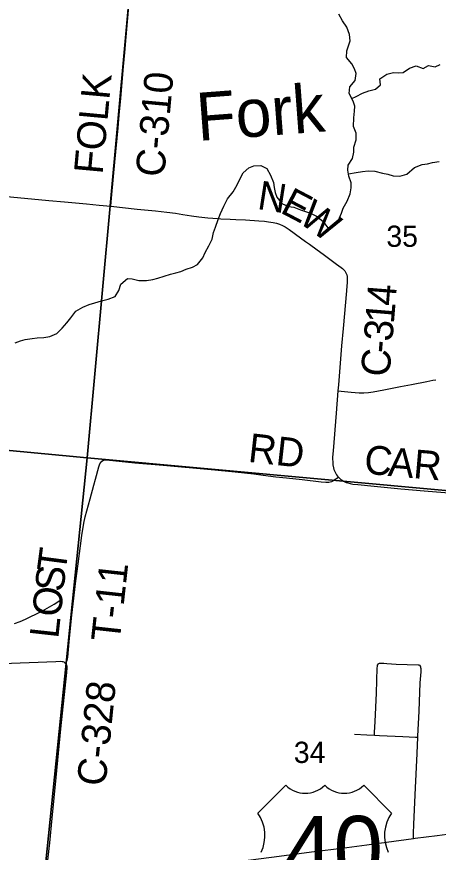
# Model space of a CAD drawing. Extents: x 831 to 1552, y 430 to 870.
# Drawn here: x 1326.79 to 1343.42, y 727.92 to 760.87 of the extents above; entities that cross this region are included whole.
import ezdxf

# ---------------------------------------------------------------- set-up
doc = ezdxf.new("R2010")
doc.units = 0
for name, color, linetype in [('GM_X_Corporation', 7, 'Continuous'), ('GM_X_County_Road', 7, 'Continuous'), ('GM_X_County_Road_Text', 7, 'Continuous'), ('GM_X_Minor_River', 7, 'Continuous'), ('GM_X_Minor_River_Text', 7, 'Continuous'), ('GM_X_Section_Text', 7, 'Continuous'), ('GM_X_Township_Road', 7, 'Continuous'), ('GM_X_Township_Road_Text', 7, 'Continuous'), ('GM_X_US_Location', 7, 'Continuous'), ('GM_X_US_Route', 7, 'Continuous'), ('GM_X_US_Shield', 7, 'Continuous')]:
    doc.layers.add(name, color=color, linetype=linetype)

msp = doc.modelspace()

# ---------------------------------------------------------------- linework, layer by layer
at = {"layer": 'GM_X_Corporation'}
for points in [[(1311.293, 765.037), (1331.382, 763.355), (1329.567, 743.48), (1309.391, 745.383)], [(1331.382, 763.355), (1350.153, 761.603), (1348.747, 741.721), (1329.567, 743.48)], [(1309.391, 745.383), (1329.567, 743.48), (1327.468, 722.912), (1307.365, 724.655)], [(1329.567, 743.48), (1348.747, 741.721), (1347.89, 720.702), (1327.468, 722.912)]]:
    msp.add_lwpolyline(points, close=True, dxfattribs=at)
at = {"layer": 'GM_X_County_Road'}
for points in [[(1330.507, 753.392), (1330.529, 753.708), (1330.657, 755.129), (1330.785, 756.488), (1330.829, 756.982), (1330.891, 757.662), (1331.003, 758.898), (1331.053, 759.454), (1331.11, 760.072), (1331.202, 761.123), (1331.371, 763.04), (1331.398, 763.338)], [(1313.508, 754.996), (1313.902, 754.958), (1314.52, 754.899), (1315.51, 754.81), (1316.315, 754.736), (1316.748, 754.701), (1317.119, 754.672), (1318.415, 754.564), (1318.724, 754.536), (1319.094, 754.496), (1319.65, 754.432), (1320.33, 754.363), (1321.009, 754.292), (1321.503, 754.241), (1322.431, 754.151), (1323.544, 754.044), (1324.596, 753.945), (1328.059, 753.623), (1328.678, 753.565), (1329.111, 753.524), (1329.544, 753.485), (1330.044, 753.438), (1330.507, 753.392)], [(1330.507, 753.392), (1331.546, 753.285), (1332.263, 753.215), (1332.706, 753.165), (1333.058, 753.115), (1333.348, 753.07), (1333.687, 753.012), (1333.967, 752.975), (1334.331, 752.937), (1334.521, 752.921), (1334.714, 752.908), (1334.841, 752.902), (1335.206, 752.886), (1335.426, 752.875), (1335.813, 752.857), (1336.341, 752.824), (1336.563, 752.805), (1336.726, 752.786), (1336.911, 752.757), (1337.033, 752.728), (1337.153, 752.69), (1337.268, 752.639), (1337.378, 752.579), (1337.535, 752.475), (1337.986, 752.149), (1338.186, 752.004), (1338.338, 751.895), (1338.639, 751.674), (1338.874, 751.503), (1339.093, 751.344), (1339.406, 751.115), (1339.588, 750.981), (1339.641, 750.94), (1339.696, 750.887), (1339.729, 750.842), (1339.762, 750.794), (1339.788, 750.745), (1339.806, 750.692), (1339.818, 750.628), (1339.825, 750.558), (1339.826, 750.479), (1339.819, 750.369), (1339.811, 750.258), (1339.794, 750.06), (1339.662, 748.574), (1339.599, 747.894), (1339.476, 746.346), (1339.459, 746.111)], [(1339.459, 746.111), (1339.388, 745.235), (1339.266, 743.748), (1339.251, 743.501), (1339.249, 743.417), (1339.252, 743.316), (1339.263, 743.194), (1339.284, 743.074), (1339.301, 743.015), (1339.321, 742.958), (1339.346, 742.903), (1339.376, 742.85), (1339.409, 742.8), (1339.446, 742.751), (1339.477, 742.716)], [(1339.477, 742.716), (1339.486, 742.706), (1339.53, 742.663), (1339.576, 742.624), (1339.625, 742.588), (1339.677, 742.556), (1339.73, 742.528), (1339.786, 742.504), (1339.844, 742.484), (1339.938, 742.461), (1340.043, 742.442), (1340.247, 742.417), (1340.891, 742.358), (1341.938, 742.256), (1342.866, 742.172), (1343.671, 742.101), (1344.723, 742.01), (1346.323, 741.894), (1346.979, 741.841), (1347.971, 741.752), (1348.778, 741.677)], [(1326.234, 735.361), (1328.329, 735.448), (1328.533, 735.453), (1328.576, 735.449), (1328.611, 735.441), (1328.644, 735.426), (1328.673, 735.409), (1328.716, 735.376)], [(1328.716, 735.376), (1328.74, 735.344), (1328.754, 735.309), (1328.765, 735.252), (1328.767, 735.193), (1328.753, 735.009), (1328.683, 734.389), (1328.52, 732.783), (1328.332, 730.867), (1328.253, 730.063), (1328.172, 729.264), (1328.078, 728.292), (1328.006, 727.612), (1327.953, 727.06), (1327.897, 726.561)]]:
    msp.add_lwpolyline(points, dxfattribs=at)
at = {"layer": 'GM_X_Minor_River'}
for points in [[(1335.617, 754.512), (1335.726, 754.708), (1335.949, 754.91), (1336.148, 754.992), (1336.413, 754.996), (1336.655, 754.887), (1336.804, 754.619), (1336.914, 754.329), (1336.942, 754.138), (1336.985, 753.94), (1337.051, 753.749), (1337.253, 753.496), (1337.51, 753.379), (1337.715, 753.362), (1337.979, 753.252), (1338.176, 753.181), (1338.373, 753.118), (1338.614, 753.009), (1338.862, 752.801), (1339.064, 752.547), (1339.316, 752.62), (1339.486, 752.846), (1339.596, 753.119), (1339.667, 753.315), (1339.83, 753.595), (1339.94, 753.89), (1339.981, 754.117), (1339.983, 754.315), (1339.895, 754.575), (1339.845, 754.818), (1339.863, 755.008), (1340.033, 755.272), (1340.09, 755.522), (1340.092, 755.72), (1340.179, 756.008), (1340.175, 756.274), (1340.079, 756.533), (1340.084, 756.883), (1340.11, 757.149), (1340.128, 757.339), (1340.062, 757.537), (1339.906, 757.835), (1339.932, 758.109), (1340.133, 758.357), (1340.182, 758.622), (1340.116, 758.813), (1340.004, 759.005), (1339.802, 759.265), (1339.806, 759.524), (1339.877, 759.721), (1339.94, 759.917), (1339.913, 760.169), (1339.81, 760.451), (1339.646, 760.704), (1339.497, 760.972)], [(1340.004, 757.648), (1340.178, 757.726), (1340.423, 757.852), (1340.682, 757.948), (1340.941, 758.013), (1341.133, 758.178), (1341.106, 758.422), (1341.39, 758.608), (1341.649, 758.666), (1341.838, 758.656), (1342.036, 758.669), (1342.289, 758.833), (1342.548, 758.936), (1342.82, 758.819), (1343.035, 758.938), (1343.3, 758.897), (1343.491, 758.986)], [(1339.875, 754.672), (1340.178, 754.723), (1340.429, 754.758), (1340.658, 754.794), (1340.916, 754.783), (1341.219, 754.703), (1341.431, 754.655), (1341.643, 754.599), (1341.901, 754.574), (1342.183, 754.654), (1342.483, 754.916), (1342.788, 755.034), (1342.993, 755.07), (1343.184, 755.113), (1343.458, 755.163)], [(1326.73, 748.005), (1326.936, 748.086), (1327.127, 748.137), (1327.393, 748.18), (1327.591, 748.2), (1327.865, 748.22), (1328.101, 748.262), (1328.376, 748.381), (1328.576, 748.591), (1328.769, 748.802), (1328.923, 748.997), (1329.124, 749.253), (1329.392, 749.417), (1329.651, 749.521), (1329.873, 749.586), (1330.139, 749.659), (1330.399, 749.732), (1330.673, 749.835), (1330.813, 750.077), (1330.9, 750.327), (1331.153, 750.544), (1331.343, 750.534), (1331.608, 750.47), (1331.904, 750.467), (1332.163, 750.509), (1332.354, 750.552), (1332.857, 750.714), (1333.063, 750.772), (1333.261, 750.823), (1333.467, 750.912), (1333.719, 750.992), (1333.918, 751.096), (1334.126, 751.36), (1334.22, 751.564), (1334.368, 751.828), (1334.493, 752.1), (1334.557, 752.365), (1334.628, 752.57), (1334.738, 752.865), (1334.825, 753.107), (1334.957, 753.402), (1335.098, 753.682), (1335.322, 753.96), (1335.485, 754.239), (1335.617, 754.512)], [(1326.705, 736.947), (1326.919, 737.021), (1327.14, 737.117), (1327.347, 737.221), (1327.538, 737.31), (1327.805, 737.443), (1327.996, 737.54), (1328.264, 737.704), (1328.532, 737.875)]]:
    msp.add_lwpolyline(points, dxfattribs=at)
at = {"layer": 'GM_X_Township_Road'}
for points in [[(1339.459, 746.111), (1339.984, 746.06), (1340.292, 746.041), (1340.477, 746.039), (1340.661, 746.049), (1340.845, 746.072), (1341.269, 746.153), (1341.934, 746.283), (1342.358, 746.364), (1342.962, 746.49), (1343.204, 746.532), (1343.326, 746.549)], [(1328.716, 735.376), (1328.751, 735.426), (1328.775, 735.477), (1328.789, 735.529), (1328.8, 735.608), (1328.858, 736.217), (1328.959, 737.267), (1329.036, 737.946), (1329.115, 738.624), (1329.209, 739.3), (1329.363, 740.407), (1329.441, 740.897), (1329.489, 741.142), (1329.55, 741.383), (1329.687, 741.86), (1329.837, 742.398), (1329.902, 742.637), (1330.03, 743.118), (1330.071, 743.238), (1330.103, 743.295), (1330.148, 743.344), (1330.206, 743.378), (1330.229, 743.383), (1330.271, 743.392), (1330.335, 743.393), (1331.448, 743.282), (1332.561, 743.182), (1334.601, 742.998), (1335.403, 742.919), (1336.145, 742.845), (1336.514, 742.796), (1337.005, 742.726), (1337.437, 742.679), (1338.054, 742.614), (1338.795, 742.524), (1338.98, 742.51), (1339.04, 742.51), (1339.1, 742.513), (1339.158, 742.522), (1339.214, 742.54), (1339.266, 742.568), (1339.315, 742.603), (1339.477, 742.716)], [(1341.054, 735.354), (1341.079, 735.368), (1341.105, 735.377), (1341.137, 735.383), (1341.177, 735.383), (1341.275, 735.374), (1341.392, 735.363), (1341.763, 735.341), (1342.627, 735.314), (1342.657, 735.308), (1342.688, 735.297)], [(1340.904, 732.539), (1340.908, 732.641), (1340.928, 733.076), (1340.977, 734.194), (1341.012, 735.188), (1341.018, 735.251), (1341.027, 735.304), (1341.054, 735.354)], [(1342.608, 732.459), (1342.61, 732.501), (1342.658, 733.491), (1342.71, 734.606), (1342.738, 735.039), (1342.743, 735.105), (1342.743, 735.154), (1342.736, 735.197), (1342.729, 735.226), (1342.719, 735.257), (1342.688, 735.297)], [(1340.112, 732.582), (1340.604, 732.55), (1340.904, 732.539)], [(1340.904, 732.539), (1341.098, 732.532), (1342.025, 732.491), (1342.519, 732.464), (1342.608, 732.459)], [(1342.438, 728.463), (1342.443, 728.661), (1342.452, 729.033), (1342.518, 730.458), (1342.581, 731.82), (1342.608, 732.459)]]:
    msp.add_lwpolyline(points, dxfattribs=at)
at = {"layer": 'GM_X_US_Route'}
msp.add_lwpolyline([(1327.897, 726.561), (1329.462, 726.76), (1330.817, 726.937), (1331.679, 727.052), (1332.603, 727.174), (1334.144, 727.374), (1335.915, 727.605), (1336.839, 727.726), (1338.525, 727.95), (1339.611, 728.089), (1340.596, 728.22), (1342.438, 728.463), (1342.506, 728.472), (1343.368, 728.587), (1345.154, 728.821), (1346.632, 729.017), (1347.232, 729.097), (1347.679, 729.157), (1348.231, 729.233)], dxfattribs=at)
at = {"layer": 'GM_X_US_Shield'}
for p, q in [((1337.399, 730.563), (1336.301, 729.464)), ((1341.574, 729.464), (1340.475, 730.563))]:
    msp.add_line(p, q, dxfattribs=at)
for centre, radius, start, end in [((1338.168, 731.347), 1.099, 225.573, 314.427), ((1339.706, 731.347), 1.099, 225.573, 314.427), ((1335.041, 728.582), 1.538, 334.5471, 35.0009), ((1342.834, 728.582), 1.538, 144.9991, 205.4529)]:
    msp.add_arc(centre, radius, start, end, dxfattribs=at)

# ---------------------------------------------------------------- texts
at = {"layer": 'GM_X_County_Road_Text'}
for s, height, rotation, p in [('FOLK', 1.1364, 84.782, (1330.175, 754.632)), ('C-310', 1.1364, 84.7823, (1332.604, 754.518)), ('N', 1.136, 351.0791, (1336.245, 753.289)), ('E', 1.136, 332.3463, (1337.14, 753.165)), ('W', 1.136, 324.1832, (1337.857, 752.793)), ('4', 1.136, 85.5617, (1341.722, 749.441)), ('1', 1.136, 85.3092, (1341.664, 748.738)), ('3', 1.136, 85.2169, (1341.605, 748.039)), ('-', 1.136, 85.1936, (1341.566, 747.573)), ('C', 1.136, 85.1936, (1341.488, 746.643)), ('C', 1.136, 353.7585, (1340.454, 742.868)), ('A', 1.136, 355.026, (1341.409, 742.763)), ('R', 1.136, 355.0838, (1342.406, 742.677)), ('C-328', 1.1364, 84.226, (1330.289, 730.5))]:
    msp.add_text(s, height=height, rotation=rotation, dxfattribs=at).set_placement(p)
at = {"layer": 'GM_X_Minor_River_Text'}
msp.add_text('Fork', height=1.8939, rotation=4.283, dxfattribs=at).set_placement((1333.945, 755.968))
at = {"layer": 'GM_X_Section_Text'}
for s, p in [('35', (1341.371, 751.793)), ('34', (1337.721, 731.443))]:
    msp.add_text(s, height=0.8371, rotation=0, dxfattribs=at).set_placement(p)
at = {"layer": 'GM_X_Township_Road_Text'}
for s, height, rotation, p in [('RD', 1.1364, 353.6073, (1335.887, 743.319)), ('T', 1.136, 82.4917, (1328.712, 738.918)), ('S', 1.136, 83.6341, (1328.628, 738.162)), ('T-11', 1.1364, 83.7459, (1330.849, 736.185)), ('O', 1.136, 83.7294, (1328.519, 737.169)), ('L', 1.136, 83.7303, (1328.426, 736.324))]:
    msp.add_text(s, height=height, rotation=rotation, dxfattribs=at).set_placement(p)
at = {"layer": 'GM_X_US_Location'}
for s in ['0', '/']:
    msp.add_text(s, height=0.00379, dxfattribs=at).set_placement((1338.936, 728.015))
at = {"layer": 'GM_X_US_Shield'}
msp.add_text('40', height=2.6367, dxfattribs=at).set_placement((1337.319, 726.717))

doc.saveas('drawing.dxf')
